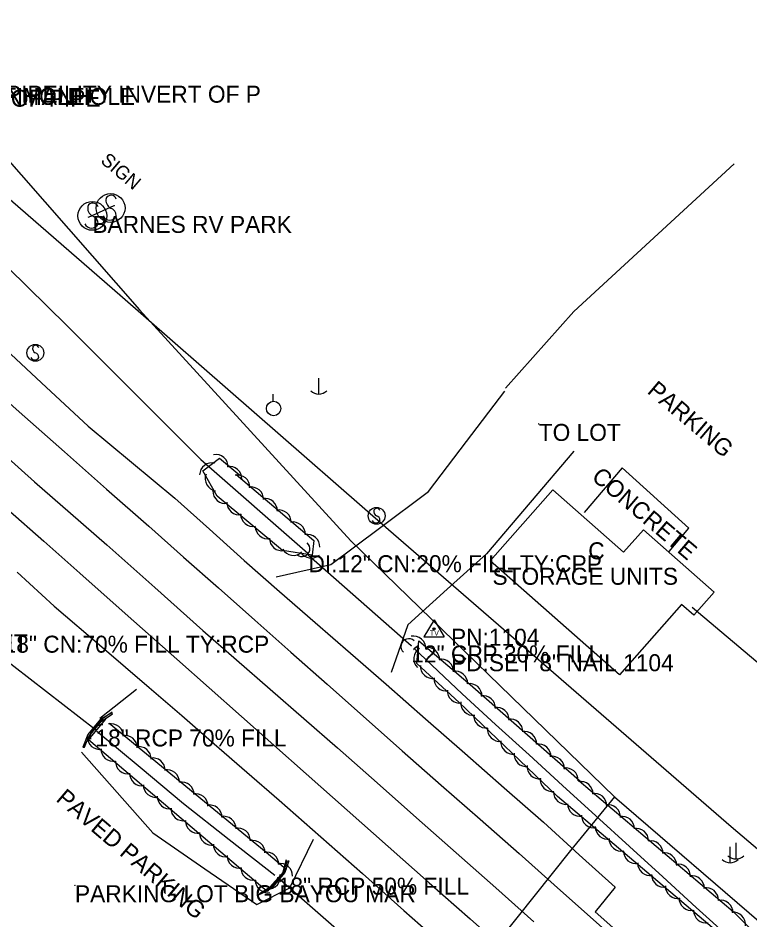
# Model space of a CAD drawing. Extents: x 1441650 to 1491889, y 345904 to 358319.
# Drawn here: x 1443564 to 1443779.5, y 356157.9 to 356423.3 of the extents above; entities that cross this region are included whole.
import ezdxf

# ---------------------------------------------------------------- set-up
doc = ezdxf.new("R2010")
doc.units = 0
for name, color, linetype in [('S_BUILDING', 7, 'Continuous'), ('S_BUILDING_ANNOT', 7, 'Continuous'), ('S_CROSS_DRAIN', 7, 'Continuous'), ('S_CROSS_DRAIN_ANNOT', 7, 'Continuous'), ('S_DITCHLINE', 7, 'Continuous'), ('S_DRG_PT_SYM', 7, 'Continuous'), ('S_EDGE_PAVEMENT', 7, 'Continuous'), ('S_GRAVEL_ROAD', 7, 'Continuous'), ('S_HEADWALL', 7, 'Continuous'), ('S_MANHOLE_ANNOT', 7, 'Continuous'), ('S_MSC_PT_SYM', 7, 'Continuous'), ('S_PARKING', 7, 'Continuous'), ('S_PARKING_ANNOT', 7, 'Continuous'), ('S_PAVEMENT_CROWN', 7, 'Continuous'), ('S_SANITARY_SEWER', 7, 'Continuous'), ('S_SANITARY_SEWER_ANNOT', 7, 'Continuous'), ('S_SECONDARY_CTL', 7, 'Continuous'), ('S_SECONDARY_CTL_ANNOT', 7, 'Continuous'), ('S_SHOULDER', 7, 'Continuous'), ('S_SIGN', 7, 'Continuous'), ('S_SIGN_ANNOT', 7, 'Continuous'), ('S_STREAM', 7, 'Continuous'), ('S_SURVEY_TEXT_ANNOT', 7, 'Continuous'), ('S_TREE', 7, 'Continuous'), ('S_UTILITY_POLE', 7, 'Continuous'), ('S_UTL_PT_SYM', 7, 'Continuous'), ('S_WATER_UTILITIES', 7, 'Continuous')]:
    doc.layers.add(name, color=color, linetype=linetype)

msp = doc.modelspace()

# ---------------------------------------------------------------- linework, layer by layer
at = {"layer": 'S_BUILDING'}
msp.add_lwpolyline([(1443741.01, 356230.01), (1443702.99, 356263.56), (1443721.43, 356284.46), (1443742.23, 356266.11), (1443748.08, 356272.73), (1443768.89, 356254.37), (1443762.89, 356247.57), (1443759.3, 356250.74)], close=True, dxfattribs=at)
at = {"layer": 'S_CROSS_DRAIN'}
for p, q in [((1443649.52, 356265.24), (1443679.77, 356238.68)), ((1443551.24, 356241.56), (1443586.8, 356213.96)), ((1443672.79, 356142.12), (1443640.48, 356170.36))]:
    msp.add_line(p, q, dxfattribs=at)
for centre, start, end in [((1443647.62, 356267.11), 229.3018, 49.631), ((1443679.01, 356238.37), 47.1037, 227.4329)]:
    msp.add_arc(centre, 2.3, start, end, dxfattribs=at)
at = {"layer": 'S_DITCHLINE'}
for points in [[(1443680.55, 356237.92), (1443694.76, 356224.43), (1443704.6, 356215.46), (1443714.45, 356206.48), (1443724.29, 356197.51), (1443734.14, 356188.54), (1443743.98, 356179.56), (1443753.82, 356170.59), (1443763.67, 356161.61), (1443773.51, 356152.64), (1443791.44, 356137.07), (1443809.37, 356121.49), (1443827.3, 356105.92), (1443845.23, 356090.35), (1443857.24, 356080), (1443869.26, 356069.66), (1443881.27, 356059.31), (1443893.28, 356048.97), (1443905.29, 356038.62), (1443917.31, 356028.27), (1443929.32, 356017.93), (1443941.33, 356007.58), (1443955.28, 355994.97)], [(1443587.26, 356213.51), (1443599.98, 356202.85), (1443612.7, 356192.19), (1443626.15, 356181.63), (1443639.6, 356171.08)]]:
    msp.add_lwpolyline(points, dxfattribs=at)
at = {"layer": 'S_DRG_PT_SYM'}
for points in [[(1443649.52, 356265.24), (1443649.52, 356265.29), (1443649.52, 356265.24), (1443649.47, 356265.24), (1443649.52, 356265.24), (1443649.52, 356265.19), (1443649.52, 356265.24), (1443649.57, 356265.24)], [(1443679.77, 356238.68), (1443679.77, 356238.73), (1443679.77, 356238.68), (1443679.72, 356238.68), (1443679.77, 356238.68), (1443679.77, 356238.63), (1443679.77, 356238.68), (1443679.82, 356238.68)], [(1443586.8, 356213.96), (1443586.8, 356214.01), (1443586.8, 356213.96), (1443586.75, 356213.96), (1443586.8, 356213.96), (1443586.8, 356213.91), (1443586.8, 356213.96), (1443586.85, 356213.96)], [(1443640.48, 356170.36), (1443640.48, 356170.41), (1443640.48, 356170.36), (1443640.43, 356170.36), (1443640.48, 356170.36), (1443640.48, 356170.31), (1443640.48, 356170.36), (1443640.53, 356170.36)]]:
    msp.add_lwpolyline(points, dxfattribs=at)
at = {"layer": 'S_EDGE_PAVEMENT'}
for points in [[(1443551.06, 356319.28), (1443564.36, 356307.47), (1443577.67, 356295.66), (1443590.07, 356284.7), (1443602.48, 356273.75), (1443612.76, 356264.68), (1443623.05, 356255.61), (1443633.7, 356246.16), (1443644.36, 356236.7), (1443655.02, 356227.25), (1443665.68, 356217.79), (1443677.13, 356207.71), (1443688.59, 356197.62), (1443700.04, 356187.54), (1443711.5, 356177.46), (1443723.71, 356166.59), (1443735.93, 356155.73)], [(1443560.96, 356278.82), (1443571.59, 356269.36), (1443582.22, 356259.91), (1443596.48, 356247.28), (1443610.73, 356234.65), (1443620.26, 356226.21), (1443629.79, 356217.77), (1443639.32, 356209.33), (1443648.85, 356200.89), (1443660.9, 356190.22), (1443672.95, 356179.55), (1443685.01, 356168.88), (1443697.06, 356158.21), (1443708.07, 356148.42)], [(1443598.89, 356225.77), (1443588.09, 356217.19)], [(1443582.73, 356207.25), (1443593.24, 356195.38), (1443603.74, 356183.52), (1443619.04, 356173.01), (1443634.33, 356162.51), (1443644.04, 356167.36), (1443651.03, 356181.7)]]:
    msp.add_lwpolyline(points, dxfattribs=at)
at = {"layer": 'S_GRAVEL_ROAD'}
for points in [[(1443639.96, 356258.85), (1443656.08, 356262.51), (1443670.45, 356273.23), (1443684.82, 356283.95), (1443696.06, 356298.72), (1443707.3, 356313.49)], [(1443727.59, 356295.81), (1443714.75, 356280.74), (1443701.92, 356265.66), (1443690.35, 356255.21), (1443678.79, 356244.77), (1443673.89, 356230.71)]]:
    msp.add_lwpolyline(points, dxfattribs=at)
at = {"layer": 'S_HEADWALL'}
for points in [[(1443591.62, 356218.84), (1443588.28, 356216.96), (1443584.6, 356212.47), (1443583.12, 356208.79), (1443583.59, 356208.77), (1443584.82, 356211.92), (1443588.53, 356216.3), (1443591.86, 356218.54)], [(1443643.73, 356175.27), (1443642.54, 356171.91), (1443638.6, 356167.18), (1443635.39, 356165.48), (1443635.14, 356165.75), (1443638.12, 356167.58), (1443642.13, 356172.12), (1443643.34, 356175.28)]]:
    msp.add_lwpolyline(points, close=True, dxfattribs=at)
for points in [[(1443591.74, 356219.1), (1443588.88, 356217.07), (1443585.51, 356213.1), (1443583.52, 356208.96)], [(1443634.96, 356165.38), (1443637.97, 356167.03), (1443641.96, 356171.73), (1443643.03, 356175.68)]]:
    msp.add_lwpolyline(points, dxfattribs=at)
at = {"layer": 'S_MSC_PT_SYM'}
for points in [[(1443592.36, 356368.1), (1443592.36, 356368.15), (1443592.36, 356368.1), (1443592.31, 356368.1), (1443592.36, 356368.1), (1443592.36, 356368.05), (1443592.36, 356368.1), (1443592.41, 356368.1)], [(1443584.8, 356364.75), (1443584.8, 356364.8), (1443584.8, 356364.75), (1443584.75, 356364.75), (1443584.8, 356364.75), (1443584.8, 356364.7), (1443584.8, 356364.75), (1443584.85, 356364.75)], [(1443717.29, 356303.87), (1443717.29, 356303.92), (1443717.29, 356303.87), (1443717.24, 356303.87), (1443717.29, 356303.87), (1443717.29, 356303.82), (1443717.29, 356303.87), (1443717.34, 356303.87)], [(1443580.78, 356168.14), (1443580.78, 356168.19), (1443580.78, 356168.14), (1443580.73, 356168.14), (1443580.78, 356168.14), (1443580.78, 356168.09), (1443580.78, 356168.14), (1443580.83, 356168.14)]]:
    msp.add_lwpolyline(points, dxfattribs=at)
at = {"layer": 'S_PARKING'}
for points in [[(1443707.55, 356314.36), (1443727.6, 356336.91), (1443774.8, 356380.37)], [(1443853.48, 356305.88), (1443793.28, 356240.57), (1443783.04, 356232.46), (1443762.49, 356249.9)], [(1443755.69, 356266.3), (1443761.51, 356273.16), (1443741.83, 356290.98), (1443730.61, 356277.77)]]:
    msp.add_lwpolyline(points, dxfattribs=at)
at = {"layer": 'S_PAVEMENT_CROWN'}
msp.add_lwpolyline([(1443555.37, 356298.87), (1443568.83, 356286.87), (1443579.48, 356277.6), (1443590.14, 356268.34), (1443604.28, 356255.71), (1443618.42, 356243.07), (1443628.33, 356234.44), (1443638.24, 356225.8), (1443648.15, 356217.17), (1443658.06, 356208.53), (1443669.7, 356198.24), (1443681.34, 356187.95), (1443692.98, 356177.66), (1443704.63, 356167.37), (1443715.81, 356157.37)], dxfattribs=at)
at = {"layer": 'S_SANITARY_SEWER'}
for p, q in [((1443555.89, 356374.93), (1443594.02, 356341.86)), ((1443594.02, 356341.86), (1443673.07, 356272.8)), ((1443673.07, 356272.8), (1443773.88, 356185.41)), ((1443773.88, 356185.41), (1443826.09, 356141.29))]:
    msp.add_line(p, q, dxfattribs=at)
at = {"layer": 'S_SECONDARY_CTL'}
for p, q in [((1443686.46, 356246.21), (1443683.45, 356241.25)), ((1443686.46, 356246.21), (1443689.41, 356241.25)), ((1443683.45, 356241.25), (1443689.41, 356241.25))]:
    msp.add_line(p, q, dxfattribs=at)
for radius in [0.311, 0.183, 0.103]:
    msp.add_circle((1443686.46, 356243.6), radius, dxfattribs=at)
at = {"layer": 'S_SHOULDER'}
for points in [[(1443557.26, 356328.65), (1443570.95, 356315.91), (1443584.63, 356303.16), (1443597.41, 356292.59), (1443610.2, 356282.01), (1443620.37, 356272.86), (1443630.54, 356263.7), (1443640.99, 356254.59), (1443651.45, 356245.48), (1443661.91, 356236.37), (1443672.37, 356227.26), (1443683.94, 356217.12), (1443695.52, 356206.97), (1443707.1, 356196.83), (1443718.67, 356186.69), (1443729.23, 356177.12), (1443739.78, 356167.54), (1443733.91, 356160.29), (1443748.61, 356147.31)], [(1443563.76, 356260.27), (1443574.69, 356250.25), (1443588.66, 356238.29), (1443602.63, 356226.33), (1443612.2, 356218.04), (1443621.77, 356209.74), (1443631.34, 356201.44), (1443640.91, 356193.15), (1443653.14, 356182.35), (1443665.38, 356171.55), (1443677.61, 356160.75), (1443689.85, 356149.95)]]:
    msp.add_lwpolyline(points, dxfattribs=at)
at = {"layer": 'S_SIGN'}
msp.add_line((1443584.8, 356364.75), (1443592.36, 356368.1), dxfattribs=at)
for centre, radius in [((1443591.27, 356367.39), 4.24), ((1443585.9, 356365.08), 4.24), ((1443569.12, 356324.79), 2.49), ((1443669.57, 356276.83), 2.49)]:
    msp.add_circle(centre, radius, dxfattribs=at)
for centre, radius, start, end in [((1443592.44, 356369.65), 2.55, 167.1196, 241.9813), ((1443591.4, 356369.55), 1.62, 16.5258, 156.8957), ((1443587.07, 356367.34), 2.55, 167.1196, 241.9813), ((1443586.03, 356367.24), 1.62, 16.5258, 156.8957), ((1443590.57, 356365.11), 2.38, 358.6529, 73.7063), ((1443585.2, 356362.8), 2.38, 358.6529, 73.7063), ((1443591.01, 356365.99), 2.17, 204.641, 335.359), ((1443585.64, 356363.68), 2.17, 204.641, 335.359), ((1443569.81, 356326.12), 1.5, 167.1196, 241.9813), ((1443569.2, 356326.06), 0.95, 16.5258, 156.8957), ((1443568.71, 356323.45), 1.4, 358.6529, 73.7063), ((1443568.97, 356323.97), 1.28, 204.641, 335.359), ((1443670.25, 356278.15), 1.5, 167.1196, 241.9813), ((1443669.64, 356278.09), 0.95, 16.5258, 156.8957), ((1443669.16, 356275.48), 1.4, 358.6529, 73.7063), ((1443669.41, 356276), 1.28, 204.641, 335.359)]:
    msp.add_arc(centre, radius, start, end, dxfattribs=at)
at = {"layer": 'S_STREAM'}
msp.add_lwpolyline([(1443455.59, 356456.01), (1443525.95, 356384.26), (1443578.49, 356332.69), (1443617.8, 356293.39), (1443649.35, 356265.86)], dxfattribs=at)
at = {"layer": 'S_TREE'}
for points in [[(1443628.18, 356289.03), (1443651.09, 356269.59), (1443650.61, 356265.21), (1443641.83, 356266.66), (1443622.61, 356282.66), (1443618.45, 356290.06), (1443623.33, 356293.8), (1443629.26, 356288.77)], [(1443729.2, 356198.89), (1443774.56, 356160.39), (1443787.46, 356147.55), (1443779.94, 356145.89), (1443722.84, 356194.21), (1443693.91, 356221.89), (1443681.38, 356233.36), (1443681.99, 356240.06), (1443697.11, 356227.22), (1443730.07, 356198.29)], [(1443590.89, 356215.87), (1443637.08, 356177.84), (1443642.96, 356172.89), (1443637.35, 356166.28), (1443584.75, 356210.96), (1443589.91, 356217.04)]]:
    msp.add_lwpolyline(points, dxfattribs=at)
for centre, start, end in [((1443588.9, 356211.74), 88.8788, 190.4758), ((1443588.05, 356211.75), 178.8531, 280.45), ((1443592.07, 356208.24), 178.8531, 280.45), ((1443596.35, 356204.56), 178.8531, 280.45), ((1443600.5, 356201.03), 178.8531, 280.45), ((1443604.56, 356197.62), 178.8531, 280.45), ((1443608.64, 356194.26), 178.8531, 280.45), ((1443612.65, 356190.75), 178.8531, 280.45), ((1443616.94, 356187.07), 178.8531, 280.45), ((1443621.08, 356183.54), 178.8531, 280.45), ((1443625.15, 356180.14), 178.8531, 280.45), ((1443629.22, 356176.77), 178.8531, 280.45), ((1443637.11, 356174.25), 359.1099, 100.7068), ((1443633.24, 356173.26), 178.8531, 280.45), ((1443641.19, 356170.9), 359.1099, 100.7068), ((1443637.57, 356170.6), 268.8788, 10.4758), ((1443637.52, 356169.58), 178.8531, 280.45)]:
    msp.add_arc(centre, 3.64, start, end, dxfattribs=at)
for centre, major_axis, ratio, start_param, end_param in [((1443622.25, 356291.23), (0.59, 3.59), 0.999643, 4.856076, 6.629277), ((1443621.12, 356288.79), (-2.89, -2.22), 0.999776, 3.825789, 5.598989), ((1443626.27, 356287.72), (0.59, 3.59), 0.999643, 4.856076, 6.629277), ((1443622.75, 356287.77), (-1.5, -3.32), 0.999344, 4.762478, 6.535678), ((1443628.61, 356285.18), (-2.78, 2.36), 0.999905, 3.825789, 5.598989), ((1443632.63, 356281.67), (-2.78, 2.36), 0.999905, 3.825789, 5.598989), ((1443625.01, 356284.12), (-0.45, -3.62), 0.999687, 4.826248, 6.599448), ((1443636.71, 356278.31), (-2.78, 2.36), 0.999905, 3.825789, 5.598989), ((1443629.12, 356280.8), (-0.45, -3.62), 0.999687, 4.826248, 6.599448), ((1443633.17, 356277.33), (-0.45, -3.62), 0.999687, 4.826248, 6.599448), ((1443640.78, 356274.9), (-2.78, 2.36), 0.999905, 3.825789, 5.598989), ((1443644.92, 356271.38), (-2.78, 2.36), 0.999905, 3.825789, 5.598989), ((1443637.49, 356273.7), (-0.45, -3.62), 0.999687, 4.826248, 6.599448), ((1443649.21, 356267.7), (-2.78, 2.36), 0.999905, 3.825789, 5.598989), ((1443641.67, 356270.21), (-0.45, -3.62), 0.999687, 4.826248, 6.599448), ((1443645.14, 356268.81), (0.71, 3.57), 0.999636, 2.28602, 4.059221), ((1443650.36, 356268.02), (0.71, 3.57), 0.999636, 2.28602, 4.059221), ((1443680.42, 356237.8), (1.97, 3.06), 0.999387, 5.265709, 7.038909), ((1443684.18, 356234.77), (-0.33, -3.63), 0.999997, 3.825788, 5.598989), ((1443684.5, 356234.44), (1.97, 3.06), 0.999387, 5.265709, 7.038909), ((1443688.56, 356231.03), (1.97, 3.06), 0.999387, 5.265709, 7.038909), ((1443686.1, 356232.6), (2.69, -2.46), 0.999991, 3.825789, 5.598989), ((1443690.11, 356228.93), (2.69, -2.46), 0.999991, 3.825789, 5.598989), ((1443692.71, 356227.51), (1.97, 3.06), 0.999387, 5.265709, 7.038909), ((1443696.93, 356223.84), (-3.19, -1.76), 0.999914, 2.601978, 4.375178), ((1443694.05, 356225.37), (2.69, -2.46), 0.999991, 3.825788, 5.598989), ((1443700.89, 356220.26), (-3.19, -1.76), 0.999914, 2.601978, 4.375178), ((1443697.99, 356221.77), (2.85, -2.27), 0.999991, 3.734022, 5.507222), ((1443704.91, 356216.84), (-3.19, -1.76), 0.999914, 2.601978, 4.375178), ((1443591.37, 356212.02), (-2.32, -2.81), 0.999909, 2.254992, 4.028193), ((1443701.8, 356218.03), (2.85, -2.27), 0.999991, 3.734022, 5.507222), ((1443708.92, 356213.36), (-3.19, -1.76), 0.999914, 2.601978, 4.375178), ((1443705.85, 356214.1), (2.85, -2.27), 0.999991, 3.734022, 5.507222), ((1443713.01, 356209.77), (-3.19, -1.76), 0.999914, 2.601978, 4.375178), ((1443595.45, 356208.58), (-2.32, -2.81), 0.999909, 2.254992, 4.028193), ((1443709.78, 356210.34), (2.85, -2.27), 0.999991, 3.734022, 5.507222), ((1443599.57, 356205.27), (-2.32, -2.81), 0.999909, 2.254992, 4.028193), ((1443717.23, 356206.02), (-3.19, -1.76), 0.999914, 2.601978, 4.375178), ((1443603.69, 356201.93), (-2.32, -2.81), 0.999909, 2.254992, 4.028193), ((1443713.64, 356206.7), (2.85, -2.27), 0.999991, 3.734022, 5.507222), ((1443721.19, 356202.45), (-3.19, -1.76), 0.999914, 2.601978, 4.375178), ((1443717.51, 356203.1), (2.85, -2.27), 0.999991, 3.734022, 5.507222), ((1443725.21, 356199.02), (-3.19, -1.76), 0.999914, 2.601978, 4.375178), ((1443607.89, 356198.47), (-2.32, -2.81), 0.999909, 2.254992, 4.028193), ((1443612.22, 356194.86), (-2.32, -2.81), 0.999909, 2.254992, 4.028193), ((1443721.31, 356199.36), (2.85, -2.27), 0.999991, 3.734022, 5.507222), ((1443729.63, 356195.03), (-3.57, -0.74), 0.999972, 2.917509, 4.69071), ((1443616.29, 356191.41), (-2.32, -2.81), 0.999909, 2.254992, 4.028193), ((1443725.29, 356195.58), (3.27, 1.62), 0.999934, 2.664133, 4.437334), ((1443733.65, 356191.52), (-3.57, -0.74), 0.999972, 2.917509, 4.69071), ((1443620.42, 356188.11), (-2.32, -2.81), 0.999909, 2.254992, 4.028193), ((1443729.44, 356192.07), (3.27, 1.62), 0.999934, 2.664133, 4.437334), ((1443737.73, 356188.16), (-3.57, -0.74), 0.999972, 2.917509, 4.69071), ((1443624.54, 356184.77), (-2.32, -2.81), 0.999909, 2.254992, 4.028193), ((1443733.51, 356188.67), (3.27, 1.62), 0.999934, 2.664133, 4.437334), ((1443741.79, 356184.76), (-3.57, -0.74), 0.999972, 2.917509, 4.69071), ((1443628.74, 356181.31), (-2.32, -2.81), 0.999909, 2.254992, 4.028193), ((1443737.59, 356185.31), (3.27, 1.62), 0.999934, 2.664133, 4.437334), ((1443745.94, 356181.23), (-3.57, -0.74), 0.999972, 2.917509, 4.69071), ((1443633.07, 356177.69), (-2.32, -2.81), 0.999909, 2.254992, 4.028193), ((1443741.62, 356181.81), (3.27, 1.62), 0.999934, 2.664133, 4.437334), ((1443750.22, 356177.56), (-3.57, -0.74), 0.999972, 2.917509, 4.69071), ((1443745.91, 356178.14), (3.27, 1.62), 0.999934, 2.664133, 4.437334), ((1443754.24, 356174.05), (-3.57, -0.74), 0.999972, 2.917509, 4.69071), ((1443750.06, 356174.62), (3.27, 1.62), 0.999934, 2.664133, 4.437334), ((1443758.32, 356170.69), (-3.57, -0.74), 0.999972, 2.917509, 4.69071), ((1443754.13, 356171.22), (3.27, 1.62), 0.999934, 2.664133, 4.437334), ((1443762.38, 356167.28), (-3.57, -0.74), 0.999972, 2.917509, 4.69071), ((1443758.21, 356167.86), (3.27, 1.62), 0.999934, 2.664133, 4.437334), ((1443766.53, 356163.76), (-3.57, -0.74), 0.999972, 2.917509, 4.69071), ((1443762.23, 356164.36), (3.27, 1.62), 0.999934, 2.664133, 4.437334), ((1443770.81, 356160.08), (-3.57, -0.74), 0.999972, 2.917509, 4.69071), ((1443766.52, 356160.69), (3.27, 1.62), 0.999934, 2.664133, 4.437334), ((1443774.53, 356156.56), (-2.91, -2.19), 0.999598, 2.399337, 4.172538)]:
    msp.add_ellipse(centre, major_axis=major_axis, ratio=ratio, start_param=start_param, end_param=end_param, dxfattribs=at)
at = {"layer": 'S_UTILITY_POLE'}
for p, q in [((1443652.48, 356317.36), (1443652.48, 356312.63)), ((1443639.12, 356310.55), (1443639.12, 356312.66)), ((1443773.57, 356179.46), (1443773.57, 356174.73)), ((1443775.27, 356180.59), (1443775.27, 356175.86))]:
    msp.add_line(p, q, dxfattribs=at)
msp.add_circle((1443639.25, 356308.41), 2.13, dxfattribs=at)
for centre in [(1443652.54, 356316.06), (1443775.34, 356179.29), (1443773.63, 356178.16)]:
    msp.add_arc(centre, 3.41, 226.3972, 313.6028, dxfattribs=at)
at = {"layer": 'S_UTL_PT_SYM'}
for points in [[(1443594.02, 356341.86), (1443594.02, 356341.91), (1443594.02, 356341.86), (1443593.97, 356341.86), (1443594.02, 356341.86), (1443594.02, 356341.81), (1443594.02, 356341.86), (1443594.07, 356341.86)], [(1443599.76, 356337.41), (1443599.76, 356337.46), (1443599.76, 356337.41), (1443599.71, 356337.41), (1443599.76, 356337.41), (1443599.76, 356337.36), (1443599.76, 356337.41), (1443599.81, 356337.41)], [(1443673.07, 356272.8), (1443673.07, 356272.85), (1443673.07, 356272.8), (1443673.02, 356272.8), (1443673.07, 356272.8), (1443673.07, 356272.75), (1443673.07, 356272.8), (1443673.12, 356272.8)], [(1443662.02, 356269.46), (1443662.02, 356269.51), (1443662.02, 356269.46), (1443661.97, 356269.46), (1443662.02, 356269.46), (1443662.02, 356269.41), (1443662.02, 356269.46), (1443662.07, 356269.46)], [(1443739.55, 356194.15), (1443739.55, 356194.2), (1443739.55, 356194.15), (1443739.5, 356194.15), (1443739.55, 356194.15), (1443739.55, 356194.1), (1443739.55, 356194.15), (1443739.6, 356194.15)], [(1443739.55, 356194.15), (1443739.55, 356194.2), (1443739.55, 356194.15), (1443739.5, 356194.15), (1443739.55, 356194.15), (1443739.55, 356194.1), (1443739.55, 356194.15), (1443739.6, 356194.15)], [(1443773.88, 356185.41), (1443773.88, 356185.46), (1443773.88, 356185.41), (1443773.83, 356185.41), (1443773.88, 356185.41), (1443773.88, 356185.36), (1443773.88, 356185.41), (1443773.93, 356185.41)], [(1443726.64, 356178.37), (1443726.64, 356178.42), (1443726.64, 356178.37), (1443726.59, 356178.37), (1443726.64, 356178.37), (1443726.64, 356178.32), (1443726.64, 356178.37), (1443726.69, 356178.37)]]:
    msp.add_lwpolyline(points, dxfattribs=at)
at = {"layer": 'S_WATER_UTILITIES'}
for p, q in [((1443556.16, 356387.17), (1443599.76, 356337.41)), ((1443599.76, 356337.41), (1443662.02, 356269.46)), ((1443662.02, 356269.46), (1443739.55, 356194.15)), ((1443739.55, 356194.15), (1443726.64, 356178.37)), ((1443739.55, 356194.15), (1443830.87, 356115.5)), ((1443726.64, 356178.37), (1443673.63, 356111.94))]:
    msp.add_line(p, q, dxfattribs=at)

# ---------------------------------------------------------------- texts
at = {"layer": 'S_BUILDING_ANNOT'}
for s, height, p in [('C', 5, (1443731.86, 356264.04)), ('STORAGE UNITS', 5.0003, (1443703.66, 356256.54))]:
    msp.add_text(s, height=height, dxfattribs=at).set_placement(p)
at = {"layer": 'S_CROSS_DRAIN_ANNOT'}
for s, p in [('DI:12" CN:20% FILL TY:CPP', (1443649.52, 356260.24)), ('DI:18" CN:70% FILL TY:RCP', (1443551.24, 356236.56)), ('12" CPP 30% FILL', (1443679.77, 356233.68)), ('18" RCP 70% FILL', (1443586.8, 356208.96)), ('18" RCP 50% FILL', (1443640.48, 356165.36))]:
    msp.add_text(s, height=5, dxfattribs=at).set_placement(p)
at = {"layer": 'S_MANHOLE_ANNOT'}
for s in ['TOP OF MANHOLE', 'BOTTOM OF MANHOLE']:
    msp.add_text(s, height=5, dxfattribs=at).set_placement((1443523.82, 356397.75))
at = {"layer": 'S_PARKING_ANNOT'}
for s, height, p in [('PARKING', 5, (1443748.93, 356313.12)), ('CONCRETE', 5, (1443732.53, 356287.77)), ('PAVED PARKING', 5.0003, (1443574.92, 356193.1))]:
    msp.add_text(s, height=height, rotation=319.6773, dxfattribs=at).set_placement(p)
at = {"layer": 'S_SANITARY_SEWER_ANNOT'}
for s, p in [('INVERT OF PIPEILITY INVERT OF P', (1443522.94, 356398.39)), ('TO INVERT OF PIPE', (1443524.41, 356397.21))]:
    msp.add_text(s, height=5, dxfattribs=at).set_placement(p)
at = {"layer": 'S_SECONDARY_CTL'}
msp.add_text('TV', height=1.5, rotation=360, dxfattribs=at).set_placement((1443685.26, 356241.59))
at = {"layer": 'S_SECONDARY_CTL_ANNOT'}
for s, p in [('PN:1104', (1443691.46, 356238.6)), ('PD:SET 8" NAIL 1104', (1443691.46, 356231.1))]:
    msp.add_text(s, height=5, dxfattribs=at).set_placement(p)
at = {"layer": 'S_SIGN_ANNOT'}
msp.add_text('SIGN', height=4, rotation=319.6773, dxfattribs=at).set_placement((1443588.07, 356380.94))
msp.add_text('BARNES RV PARK', height=5, dxfattribs=at).set_placement((1443585.9, 356360.08))
at = {"layer": 'S_SURVEY_TEXT_ANNOT'}
for s, p in [('TO LOT', (1443717.29, 356298.87)), ('BILLS BAYOU MARKET', (1443493.69, 356236.93)), ('PARKING LOT BIG BAYOU MAR', (1443580.78, 356163.14))]:
    msp.add_text(s, height=5, dxfattribs=at).set_placement(p)

doc.saveas('drawing.dxf')
